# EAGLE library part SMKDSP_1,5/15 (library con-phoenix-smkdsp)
Printklemme, Nennstrom: 17,5 A, Bemessungsspannung: 250 V, Raster: 5,0 mm Source: http://eshop.phoenixcontact.de .. 1733415.pdf
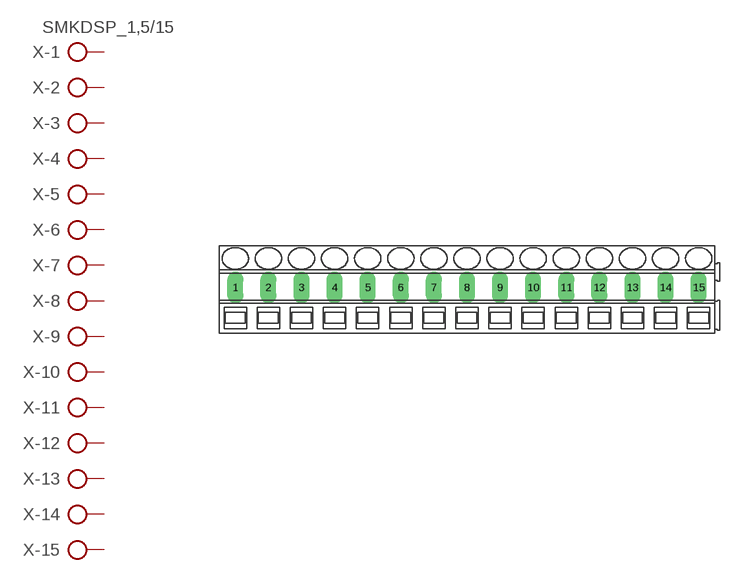
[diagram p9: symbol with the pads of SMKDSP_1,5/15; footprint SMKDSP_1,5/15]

Designator prefix X; gates -1=KLV -2=KL -3=KL -4=KL -5=KL -6=KL -7=KL -8=KL -9=KL -10=KL -11=KL -12=KL -13=KL -14=KL -15=KL

## SMKDSP_1,5/15 (OC_FARNELL: unknown; OC_NEWARK: unknown)  [SMKDSP_1,5/15]
1  -1:KL  pas
2  -2:KL  pas
3  -3:KL  pas
4  -4:KL  pas
5  -5:KL  pas
6  -6:KL  pas
7  -7:KL  pas
8  -8:KL  pas
9  -9:KL  pas
10  -10:KL  pas
11  -11:KL  pas
12  -12:KL  pas
13  -13:KL  pas
14  -14:KL  pas
15  -15:KL  pas

## Footprint SMKDSP_1,5/15 (pad centres in mm)
Printklemme, Nennstrom: 17,5 A, Bemessungsspannung: 250 V, Raster: 5,0 mm Source: http://eshop.phoenixcontact.de .. 1733415.pdf
drill 1.6 pad 1.8 long: 1 -2.5,0; 2 2.5,0; 3 7.5,0; 4 12.5,0; 5 17.5,0; 6 22.5,0; 7 27.5,0; 8 32.5,0; 9 37.5,0; 10 42.5,0; 11 47.5,0; 12 52.5,0; 13 57.5,0; 14 62.5,0; 15 67.5,0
